(* Logix 5000 project; controller Test vendor 1 type 14 code 92 rev 33.11; software revision 33.03; part 3 of 3 *)

ADD_ON_INSTRUCTION Banner_K50Display_PD_v2   (* revision 2.1, vendor Banner Engineering *)
// Takes the raw SINT information and converts that data into actual information.
VAR_IN_OUT
   PDIO : Banner_K50Display_PDIO_v2; {required}
END_VAR
VAR_INPUT
   Operation_Mode : SINT; {required}   // Linked from Parameters AOI or entered manually.
   Byte_Swap : BOOL; {required}
END_VAR
VAR
   PDO_Temp : SINT[20]; {access None}
   PDI_Temp : SINT[2]; {access None}
END_VAR

ROUTINE Logic   (* ladder *)
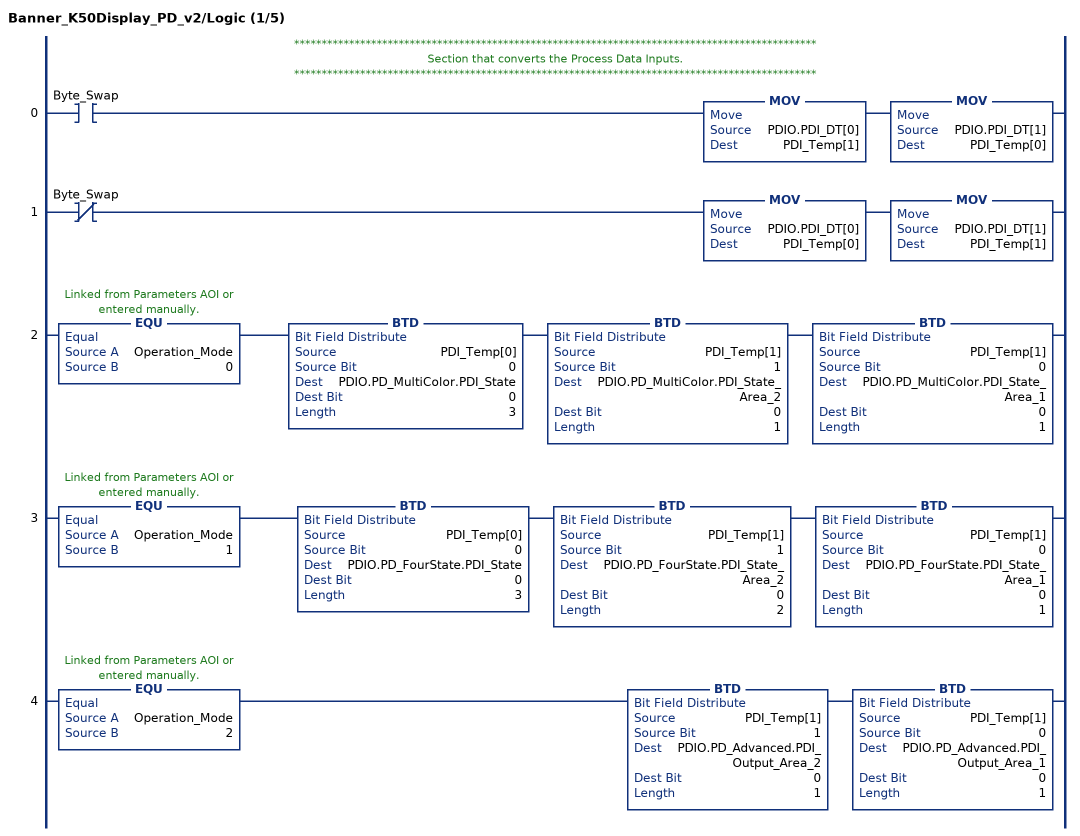
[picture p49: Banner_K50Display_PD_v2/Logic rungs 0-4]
   // ***********************************************************************************************
   // Section that converts the Process Data Inputs.
   // ***********************************************************************************************
   0: XIC(Byte_Swap)MOV(PDIO.PDI_DT[0],PDI_Temp[1])MOV(PDIO.PDI_DT[1],PDI_Temp[0]);
   1: XIO(Byte_Swap)MOV(PDIO.PDI_DT[0],PDI_Temp[0])MOV(PDIO.PDI_DT[1],PDI_Temp[1]);
   2: EQU(Operation_Mode,0)BTD(PDI_Temp[0],0,PDIO.PD_MultiColor.PDI_State,0,3)BTD(PDI_Temp[1],1,PDIO.PD_MultiColor.PDI_State_Area_2,0,1)BTD(PDI_Temp[1],0,PDIO.PD_MultiColor.PDI_State_Area_1,0,1);
   3: EQU(Operation_Mode,1)BTD(PDI_Temp[0],0,PDIO.PD_FourState.PDI_State,0,3)BTD(PDI_Temp[1],1,PDIO.PD_FourState.PDI_State_Area_2,0,2)BTD(PDI_Temp[1],0,PDIO.PD_FourState.PDI_State_Area_1,0,1);
   4: EQU(Operation_Mode,2)BTD(PDI_Temp[1],1,PDIO.PD_Advanced.PDI_Output_Area_2,0,1)BTD(PDI_Temp[1],0,PDIO.PD_Advanced.PDI_Output_Area_1,0,1);
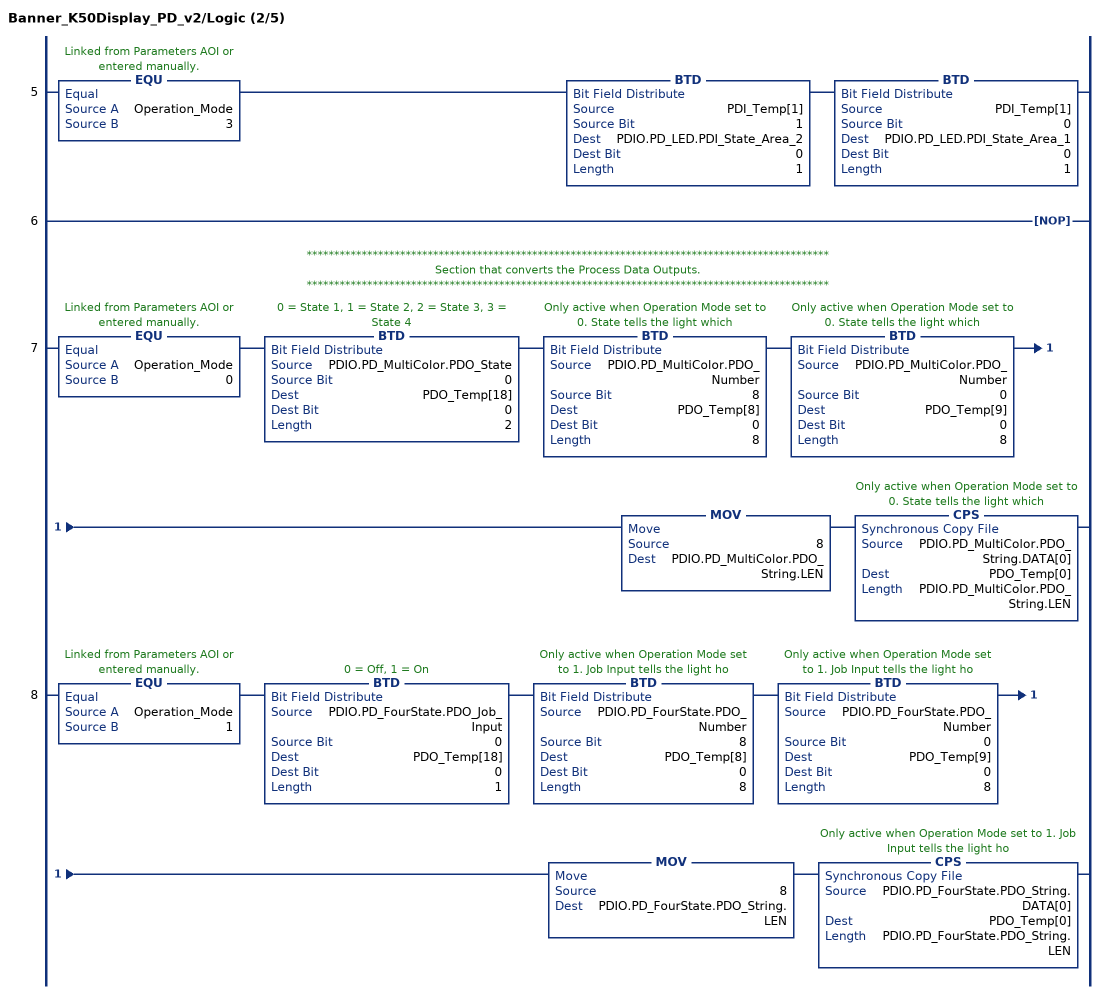
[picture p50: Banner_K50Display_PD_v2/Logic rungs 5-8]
   5: EQU(Operation_Mode,3)BTD(PDI_Temp[1],1,PDIO.PD_LED.PDI_State_Area_2,0,1)BTD(PDI_Temp[1],0,PDIO.PD_LED.PDI_State_Area_1,0,1);
   6: NOP();
   // ***********************************************************************************************
   // Section that converts the Process Data Outputs.
   // ***********************************************************************************************
   7: EQU(Operation_Mode,0)BTD(PDIO.PD_MultiColor.PDO_State,0,PDO_Temp[18],0,2)BTD(PDIO.PD_MultiColor.PDO_Number,8,PDO_Temp[8],0,8)BTD(PDIO.PD_MultiColor.PDO_Number,0,PDO_Temp[9],0,8)MOV(8,PDIO.PD_MultiColor.PDO_String.LEN)CPS(PDIO.PD_MultiColor.PDO_String.DATA[0],PDO_Temp[0],PDIO.PD_MultiColor.PDO_String.LEN);
   8: EQU(Operation_Mode,1)BTD(PDIO.PD_FourState.PDO_Job_Input,0,PDO_Temp[18],0,1)BTD(PDIO.PD_FourState.PDO_Number,8,PDO_Temp[8],0,8)BTD(PDIO.PD_FourState.PDO_Number,0,PDO_Temp[9],0,8)MOV(8,PDIO.PD_FourState.PDO_String.LEN)CPS(PDIO.PD_FourState.PDO_String.DATA[0],PDO_Temp[0],PDIO.PD_FourState.PDO_String.LEN);
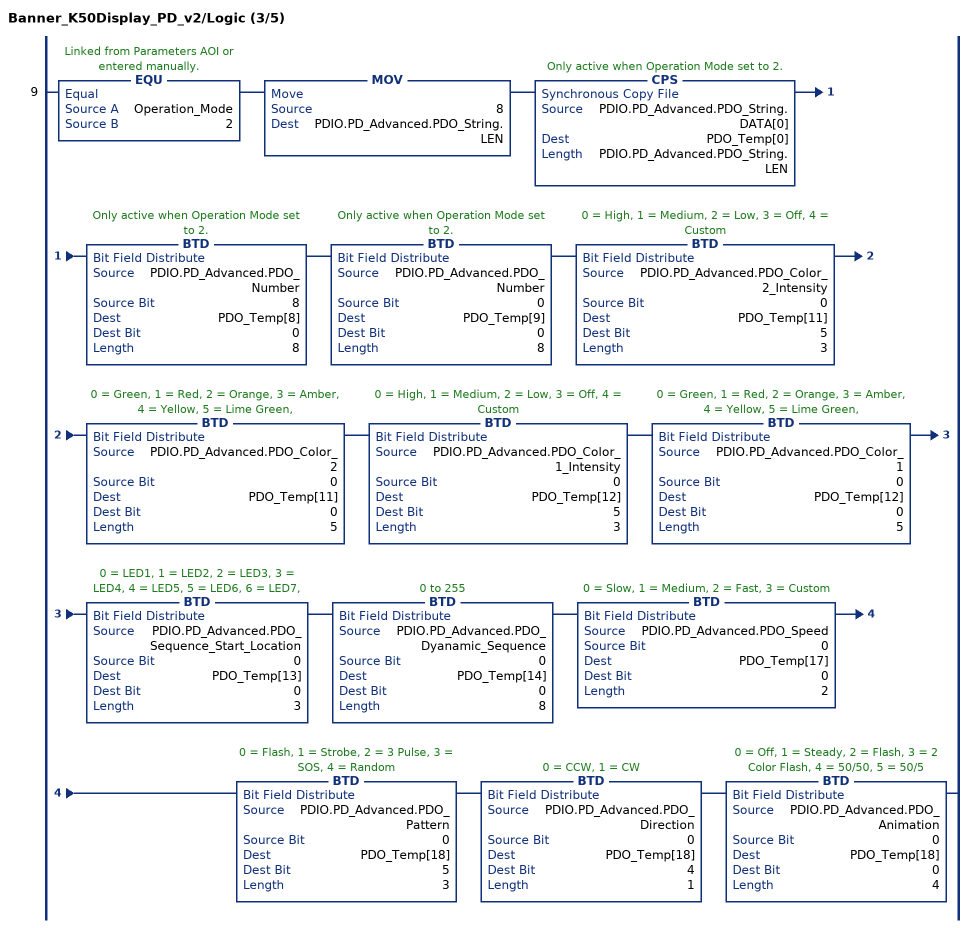
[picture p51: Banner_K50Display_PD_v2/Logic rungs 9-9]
   9: EQU(Operation_Mode,2)MOV(8,PDIO.PD_Advanced.PDO_String.LEN)CPS(PDIO.PD_Advanced.PDO_String.DATA[0],PDO_Temp[0],PDIO.PD_Advanced.PDO_String.LEN)BTD(PDIO.PD_Advanced.PDO_Number,8,PDO_Temp[8],0,8)BTD(PDIO.PD_Advanced.PDO_Number,0,PDO_Temp[9],0,8)BTD(PDIO.PD_Advanced.PDO_Color_2_Intensity,0,PDO_Temp[11],5,3)BTD(PDIO.PD_Advanced.PDO_Color_2,0,PDO_Temp[11],0,5)BTD(PDIO.PD_Advanced.PDO_Color_1_Intensity,0,PDO_Temp[12],5,3)BTD(PDIO.PD_Advanced.PDO_Color_1,0,PDO_Temp[12],0,5)BTD(PDIO.PD_Advanced.PDO_Sequence_Start_Location,0,PDO_Temp[13],0,3)BTD(PDIO.PD_Advanced.PDO_Dyanamic_Sequence,0,PDO_Temp[14],0,8)BTD(PDIO.PD_Advanced.PDO_Speed,0,PDO_Temp[17],0,2)BTD(PDIO.PD_Advanced.PDO_Pattern,0,PDO_Temp[18],5,3)BTD(PDIO.PD_Advanced.PDO_Direction,0,PDO_Temp[18],4,1)BTD(PDIO.PD_Advanced.PDO_Animation,0,PDO_Temp[18],0,4);
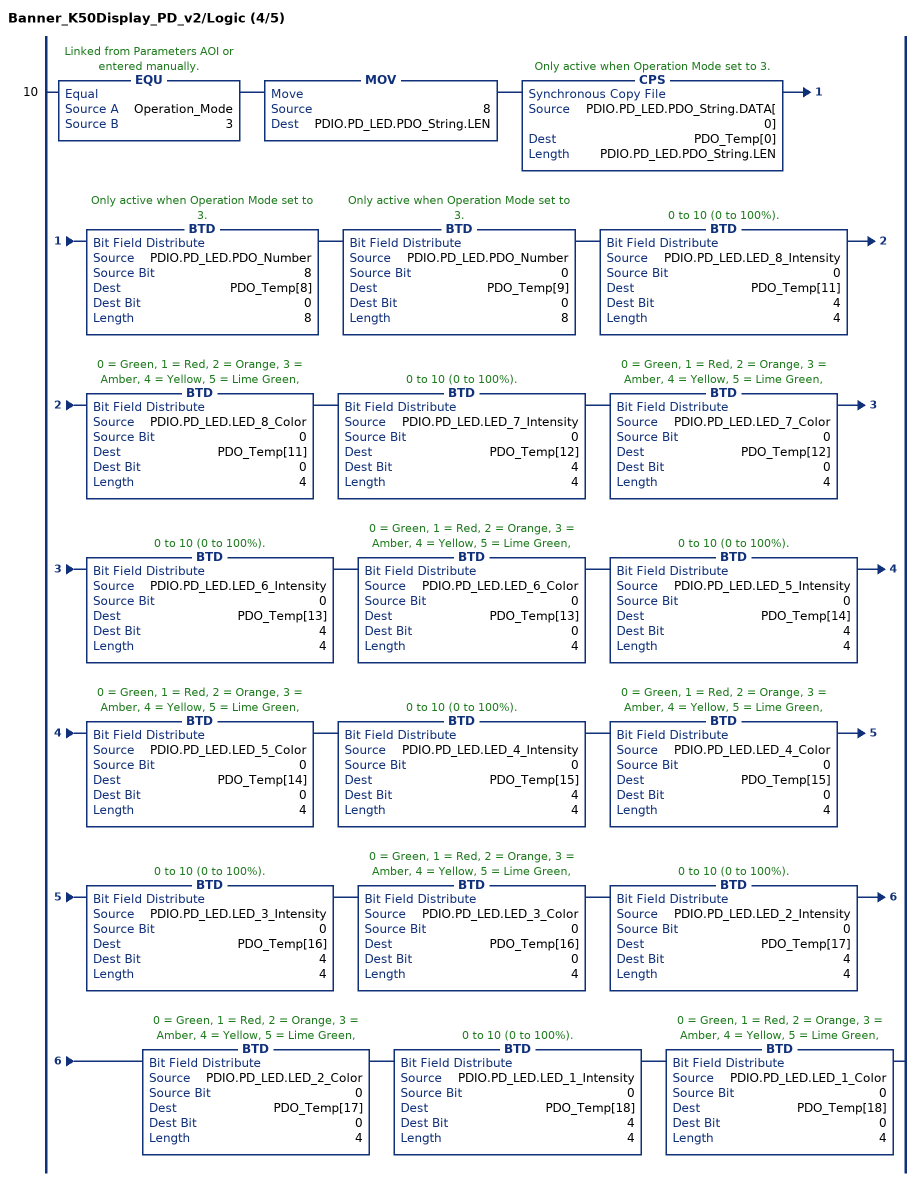
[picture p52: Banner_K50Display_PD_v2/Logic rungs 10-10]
   10: EQU(Operation_Mode,3)MOV(8,PDIO.PD_LED.PDO_String.LEN)CPS(PDIO.PD_LED.PDO_String.DATA[0],PDO_Temp[0],PDIO.PD_LED.PDO_String.LEN)BTD(PDIO.PD_LED.PDO_Number,8,PDO_Temp[8],0,8)BTD(PDIO.PD_LED.PDO_Number,0,PDO_Temp[9],0,8)BTD(PDIO.PD_LED.LED_8_Intensity,0,PDO_Temp[11],4,4)BTD(PDIO.PD_LED.LED_8_Color,0,PDO_Temp[11],0,4)BTD(PDIO.PD_LED.LED_7_Intensity,0,PDO_Temp[12],4,4)BTD(PDIO.PD_LED.LED_7_Color,0,PDO_Temp[12],0,4)BTD(PDIO.PD_LED.LED_6_Intensity,0,PDO_Temp[13],4,4)BTD(PDIO.PD_LED.LED_6_Color,0,PDO_Temp[13],0,4)BTD(PDIO.PD_LED.LED_5_Intensity,0,PDO_Temp[14],4,4)BTD(PDIO.PD_LED.LED_5_Color,0,PDO_Temp[14],0,4)BTD(PDIO.PD_LED.LED_4_Intensity,0,PDO_Temp[15],4,4)BTD(PDIO.PD_LED.LED_4_Color,0,PDO_Temp[15],0,4)BTD(PDIO.PD_LED.LED_3_Intensity,0,PDO_Temp[16],4,4)BTD(PDIO.PD_LED.LED_3_Color,0,PDO_Temp[16],0,4)BTD(PDIO.PD_LED.LED_2_Intensity,0,PDO_Temp[17],4,4)BTD(PDIO.PD_LED.LED_2_Color,0,PDO_Temp[17],0,4)BTD(PDIO.PD_LED.LED_1_Intensity,0,PDO_Temp[18],4,4)BTD(PDIO.PD_LED.LED_1_Color,0,PDO_Temp[18],0,4);
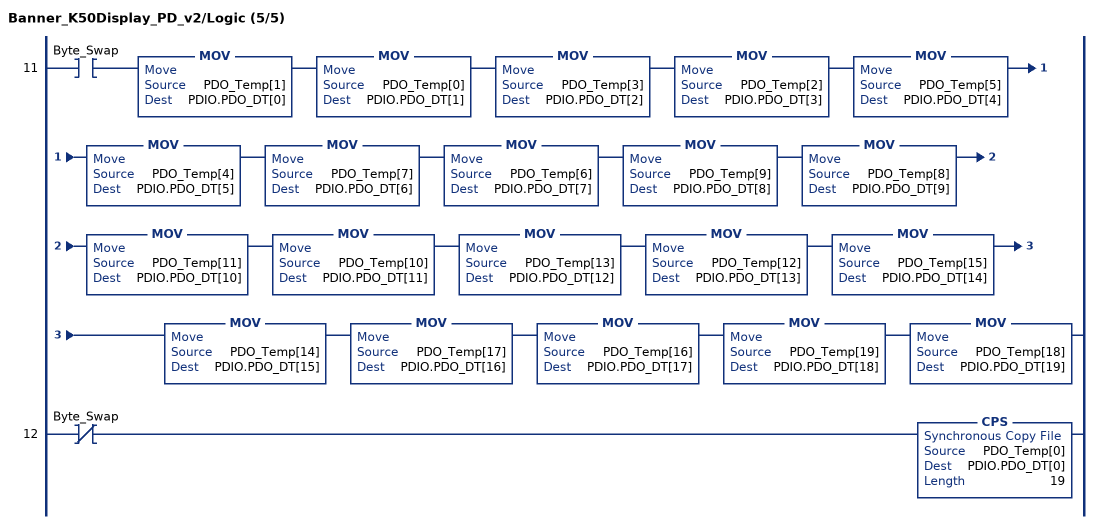
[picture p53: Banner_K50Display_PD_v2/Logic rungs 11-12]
   11: XIC(Byte_Swap)MOV(PDO_Temp[1],PDIO.PDO_DT[0])MOV(PDO_Temp[0],PDIO.PDO_DT[1])MOV(PDO_Temp[3],PDIO.PDO_DT[2])MOV(PDO_Temp[2],PDIO.PDO_DT[3])MOV(PDO_Temp[5],PDIO.PDO_DT[4])MOV(PDO_Temp[4],PDIO.PDO_DT[5])MOV(PDO_Temp[7],PDIO.PDO_DT[6])MOV(PDO_Temp[6],PDIO.PDO_DT[7])MOV(PDO_Temp[9],PDIO.PDO_DT[8])MOV(PDO_Temp[8],PDIO.PDO_DT[9])MOV(PDO_Temp[11],PDIO.PDO_DT[10])MOV(PDO_Temp[10],PDIO.PDO_DT[11])MOV(PDO_Temp[13],PDIO.PDO_DT[12])MOV(PDO_Temp[12],PDIO.PDO_DT[13])MOV(PDO_Temp[15],PDIO.PDO_DT[14])MOV(PDO_Temp[14],PDIO.PDO_DT[15])MOV(PDO_Temp[17],PDIO.PDO_DT[16])MOV(PDO_Temp[16],PDIO.PDO_DT[17])MOV(PDO_Temp[19],PDIO.PDO_DT[18])MOV(PDO_Temp[18],PDIO.PDO_DT[19]);
   12: XIO(Byte_Swap)CPS(PDO_Temp[0],PDIO.PDO_DT[0],19);
END_ROUTINE
END_ADD_ON_INSTRUCTION

VAR_GLOBAL   (* controller tags *)
   IOLM1 : Banner_IOLM_v4;
   IOLM1_Status : Banner_DXMR_IOLM_Param_v4;
   K50_IOLM1_01_Status : Banner_K50Display_Param_v4;
   K50D_IOLM1_01 : Banner_K50Display_v4;
   K50D_IOLM1_01_PD : Banner_K50Display_PDIO_v2;
   K50D_IOLM1_01_PD_Status : Banner_K50Display_PD_v2;
END_VAR

PROGRAM MainProgram   (* main routine MainRoutine *)

ROUTINE MainRoutine   (* ladder *)
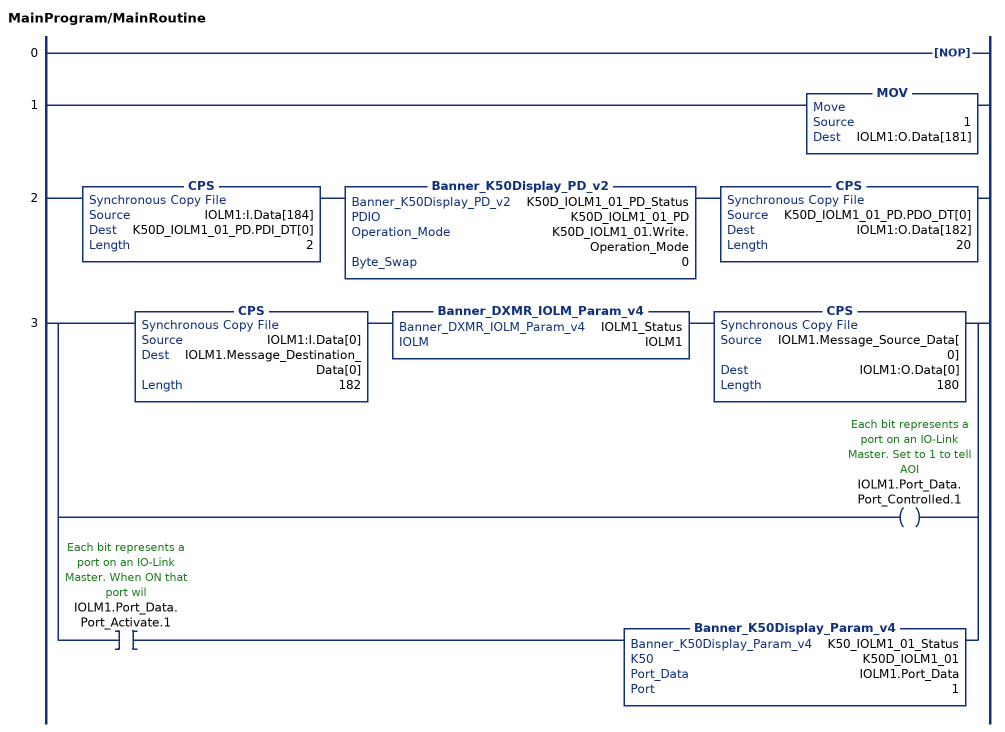
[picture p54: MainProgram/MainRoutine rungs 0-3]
   0: NOP();
   1: MOV(1,IOLM1:O.Data[181]);
   2: CPS(IOLM1:I.Data[184],K50D_IOLM1_01_PD.PDI_DT[0],2)Banner_K50Display_PD_v2(K50D_IOLM1_01_PD_Status,K50D_IOLM1_01_PD,K50D_IOLM1_01.Write.Operation_Mode,0)CPS(K50D_IOLM1_01_PD.PDO_DT[0],IOLM1:O.Data[182],20);
   3: [CPS(IOLM1:I.Data[0],IOLM1.Message_Destination_Data[0],182) Banner_DXMR_IOLM_Param_v4(IOLM1_Status,IOLM1) CPS(IOLM1.Message_Source_Data[0],IOLM1:O.Data[0],180) ,OTE(IOLM1.Port_Data.Port_Controlled.1) ,XIC(IOLM1.Port_Data.Port_Activate.1) Banner_K50Display_Param_v4(K50_IOLM1_01_Status,K50D_IOLM1_01,IOLM1.Port_Data,1) ];
END_ROUTINE
END_PROGRAM
